Omron CX-Programmer project NuevoProyecto (CX-Programmer 9.50)

# PLC NewPLC1: CP1L-E EM

## Program P7_3 (cyclic task 0)
Local symbols
Ab 100.01 BOOL
As 100.00 BOOL
B 100.02 BOOL
C 100.03 BOOL
M0_0 10.00 BOOL
M0_1 10.01 BOOL
M0_2 10.02 BOOL
M0_3 10.03 BOOL
M0_4 10.04 BOOL
M0_5 10.05 BOOL
M1_0 10.06 BOOL
M1_1 10.07 BOOL
M1_2 10.08 BOOL
M1_3 10.09 BOOL
M1_4 10.10 BOOL
M1_5 10.11 BOOL
a_0 0.01 BOOL
a_1 0.02 BOOL
a_2 0.03 BOOL
b_0 0.04 BOOL
b_1 0.05 BOOL
c_0 0.06 BOOL
c_1 0.07 BOOL
m 0.00 BOOL

### Section Sección1_Programa_principal
; Programa principal (Etapas 0 ... 7)

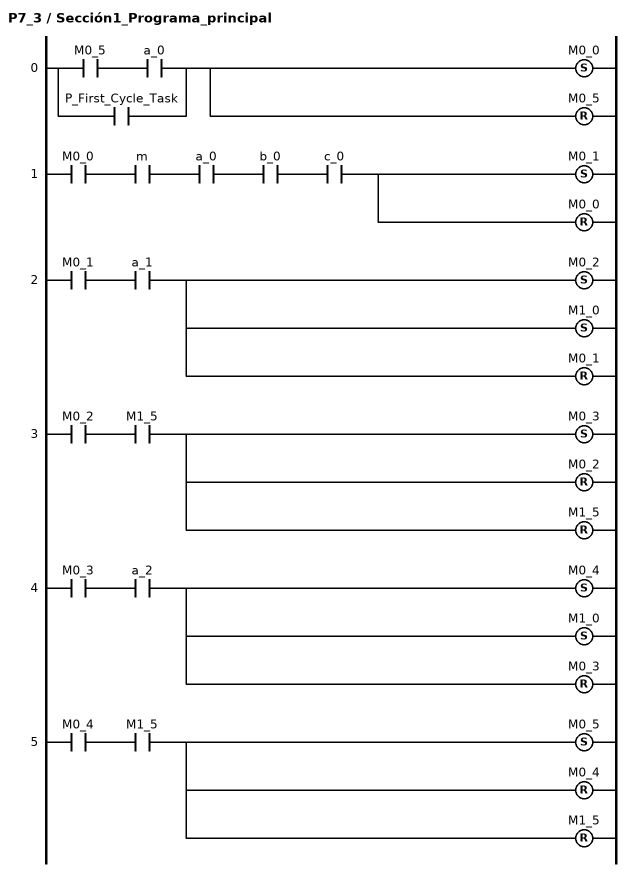
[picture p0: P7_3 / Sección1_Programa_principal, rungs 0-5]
; rung 0
LD M0_5
AND a_0
OR P_First_Cycle_Task
SET M0_0
RSET M0_5
; rung 1
LD M0_0
AND m
AND a_0
AND b_0
AND c_0
SET M0_1
RSET M0_0
; rung 2
LD M0_1
AND a_1
SET M0_2
SET M1_0
RSET M0_1
; rung 3
LD M0_2
AND M1_5
SET M0_3
RSET M0_2
RSET M1_5
; rung 4
LD M0_3
AND a_2
SET M0_4
SET M1_0
RSET M0_3
; rung 5
LD M0_4
AND M1_5
SET M0_5
RSET M0_4
RSET M1_5

### Section Sección2_Macroetapa

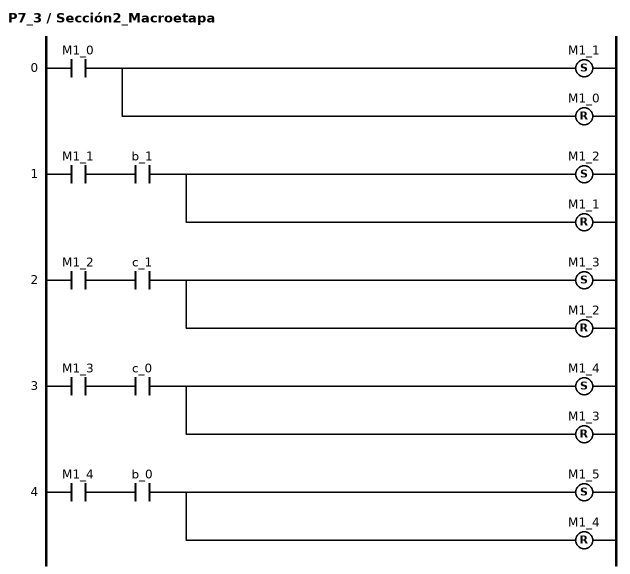
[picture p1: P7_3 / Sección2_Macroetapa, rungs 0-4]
; rung 0
LD M1_0
SET M1_1
RSET M1_0
; rung 1
LD M1_1
AND b_1
SET M1_2
RSET M1_1
; rung 2
LD M1_2
AND c_1
SET M1_3
RSET M1_2
; rung 3
LD M1_3
AND c_0
SET M1_4
RSET M1_3
; rung 4
LD M1_4
AND b_0
SET M1_5
RSET M1_4

### Section Sección3_Salidas

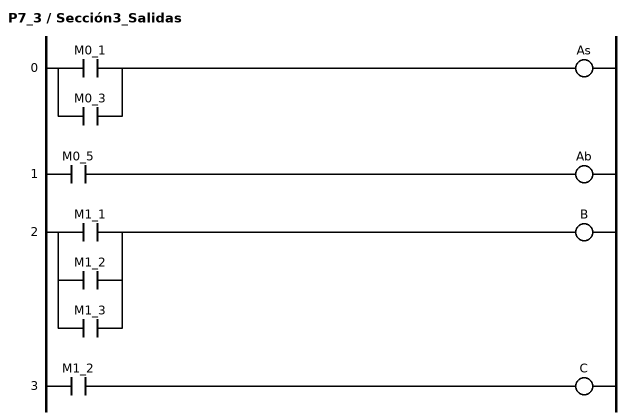
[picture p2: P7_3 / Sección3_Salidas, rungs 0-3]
; rung 0
LD M0_1
OR M0_3
OUT As
; rung 1
LD M0_5
OUT Ab
; rung 2
LD M1_1
OR M1_2
OR M1_3
OUT B
; rung 3
LD M1_2
OUT C

### Section Sección4_END
; rung 0: Fin de programa
END(001)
